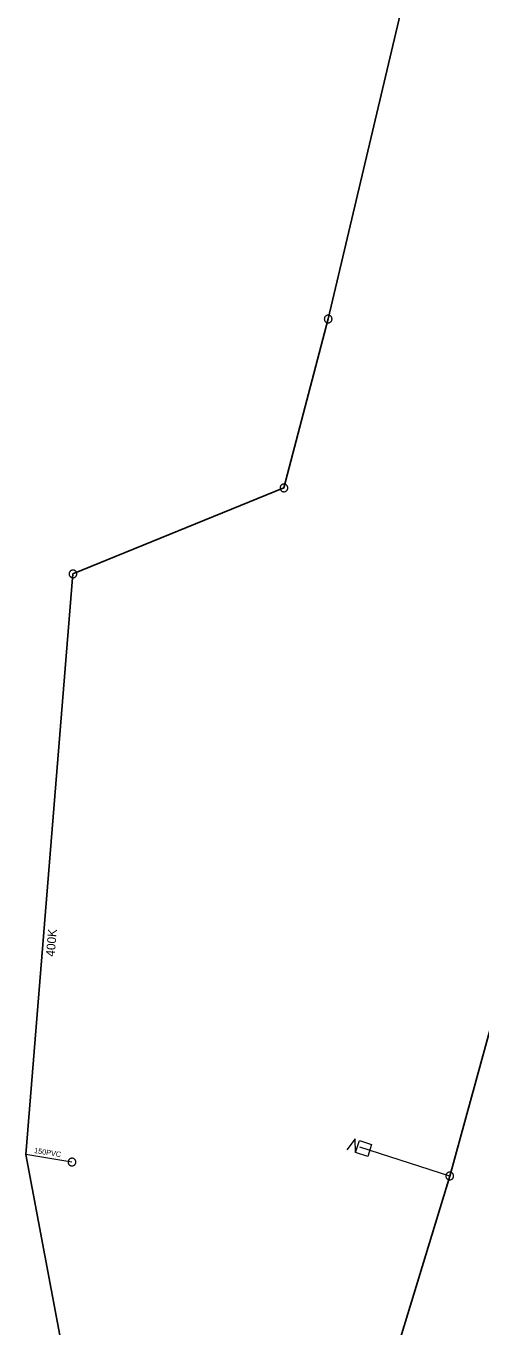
# Model space of a CAD drawing. Extents: x -741806 to -738704, y -1059275 to -1055387.
# Drawn here: x -740344.9 to -740293.4, y -1056915.4 to -1056767.8 of the extents above; entities that cross this region are included whole.
import ezdxf

# ---------------------------------------------------------------- set-up
doc = ezdxf.new("R2010")
doc.units = 0
doc.header["$LTSCALE"] = 0.4
for name, color, linetype, lineweight in [('2', 7, 'Continuous', 25), ('21', 7, 'Continuous', 13), ('3', 7, 'Continuous', 13), ('46', 7, 'Continuous', 13), ('51', 7, 'Continuous', 13), ('52', 7, 'Continuous', 25), ('56', 7, 'Continuous', 13), ('60', 7, 'Continuous', 13)]:
    doc.layers.add(name, color=color, linetype=linetype, lineweight=lineweight)
doc.layers.add('5', color=7, linetype='Continuous')
doc.layers.add('55', color=7, linetype='Continuous')

msp = doc.modelspace()

# ---------------------------------------------------------------- linework, layer by layer
at = {"layer": '2'}
for p, q in [((-740344.949, -1056895.875), (-740339.62, -1056830)), ((-740332.78, -1056960.44), (-740344.949, -1056895.875))]:
    msp.add_line(p, q, dxfattribs=at)
msp.add_lwpolyline([(-740339.62, -1056830), (-740315.66, -1056820.24), (-740310.64, -1056801.08), (-740301.43, -1056762.19), (-740297.32, -1056727.3), (-740286.155, -1056679.426), (-740260.146, -1056685.649), (-740223.28, -1056694.679), (-740203.5, -1056696.159)], dxfattribs=at)
at = {"layer": '21'}
msp.add_line((-740296.842, -1056898.301), (-740307.048, -1056895.04), dxfattribs=at)
at = {"layer": '3'}
for points in [[(-740310.528, -1056800.656), (-740310.572, -1056800.647), (-740310.618, -1056800.643), (-740310.664, -1056800.643), (-740310.709, -1056800.648), (-740310.754, -1056800.658), (-740310.798, -1056800.672), (-740310.839, -1056800.691), (-740310.879, -1056800.714), (-740310.915, -1056800.742), (-740310.949, -1056800.772), (-740310.98, -1056800.806), (-740311.007, -1056800.844), (-740311.029, -1056800.883), (-740311.048, -1056800.925), (-740311.062, -1056800.969), (-740311.071, -1056801.014), (-740311.075, -1056801.059), (-740311.076, -1056801.105), (-740311.07, -1056801.151), (-740311.06, -1056801.196), (-740311.046, -1056801.239), (-740311.027, -1056801.28), (-740311.004, -1056801.32), (-740310.977, -1056801.357), (-740310.946, -1056801.391), (-740310.911, -1056801.421), (-740310.875, -1056801.448), (-740310.835, -1056801.471), (-740310.793, -1056801.489), (-740310.749, -1056801.503), (-740310.705, -1056801.512), (-740310.659, -1056801.517), (-740310.613, -1056801.517), (-740310.567, -1056801.511), (-740310.523, -1056801.502), (-740310.479, -1056801.487), (-740310.438, -1056801.468), (-740310.398, -1056801.445), (-740310.362, -1056801.418), (-740310.328, -1056801.388), (-740310.297, -1056801.353), (-740310.27, -1056801.316), (-740310.247, -1056801.276), (-740310.229, -1056801.235), (-740310.215, -1056801.191), (-740310.206, -1056801.146), (-740310.201, -1056801.1), (-740310.201, -1056801.055), (-740310.207, -1056801.009), (-740310.217, -1056800.964), (-740310.231, -1056800.921), (-740310.249, -1056800.879), (-740310.273, -1056800.839), (-740310.3, -1056800.803), (-740310.331, -1056800.769), (-740310.365, -1056800.738), (-740310.402, -1056800.712), (-740310.443, -1056800.689), (-740310.484, -1056800.67), (-740310.527, -1056800.656)], [(-740315.254, -1056820.075), (-740315.273, -1056820.034), (-740315.297, -1056819.995), (-740315.325, -1056819.958), (-740315.356, -1056819.925), (-740315.391, -1056819.895), (-740315.428, -1056819.868), (-740315.468, -1056819.847), (-740315.511, -1056819.828), (-740315.554, -1056819.816), (-740315.599, -1056819.807), (-740315.645, -1056819.803), (-740315.691, -1056819.804), (-740315.736, -1056819.81), (-740315.781, -1056819.82), (-740315.824, -1056819.835), (-740315.866, -1056819.854), (-740315.905, -1056819.879), (-740315.941, -1056819.906), (-740315.975, -1056819.938), (-740316.005, -1056819.973), (-740316.03, -1056820.01), (-740316.052, -1056820.049), (-740316.07, -1056820.092), (-740316.084, -1056820.135), (-740316.093, -1056820.181), (-740316.096, -1056820.227), (-740316.096, -1056820.272), (-740316.09, -1056820.318), (-740316.079, -1056820.362), (-740316.064, -1056820.406), (-740316.045, -1056820.447), (-740316.021, -1056820.486), (-740315.993, -1056820.523), (-740315.961, -1056820.556), (-740315.928, -1056820.586), (-740315.89, -1056820.612), (-740315.85, -1056820.634), (-740315.807, -1056820.652), (-740315.764, -1056820.665), (-740315.719, -1056820.674), (-740315.673, -1056820.678), (-740315.627, -1056820.677), (-740315.582, -1056820.672), (-740315.537, -1056820.661), (-740315.494, -1056820.646), (-740315.452, -1056820.626), (-740315.413, -1056820.603), (-740315.377, -1056820.575), (-740315.344, -1056820.543), (-740315.314, -1056820.508), (-740315.288, -1056820.471), (-740315.265, -1056820.431), (-740315.248, -1056820.389), (-740315.234, -1056820.345), (-740315.226, -1056820.3), (-740315.222, -1056820.254), (-740315.223, -1056820.209), (-740315.229, -1056820.163), (-740315.239, -1056820.118), (-740315.253, -1056820.076)], [(-740339.578, -1056829.563), (-740339.623, -1056829.562), (-740339.669, -1056829.565), (-740339.715, -1056829.573), (-740339.758, -1056829.585), (-740339.801, -1056829.602), (-740339.842, -1056829.623), (-740339.879, -1056829.649), (-740339.915, -1056829.677), (-740339.946, -1056829.711), (-740339.975, -1056829.746), (-740340, -1056829.785), (-740340.021, -1056829.826), (-740340.036, -1056829.869), (-740340.048, -1056829.913), (-740340.054, -1056829.959), (-740340.056, -1056830.005), (-740340.053, -1056830.05), (-740340.046, -1056830.095), (-740340.033, -1056830.139), (-740340.016, -1056830.182), (-740339.994, -1056830.222), (-740339.97, -1056830.26), (-740339.94, -1056830.296), (-740339.908, -1056830.328), (-740339.871, -1056830.356), (-740339.833, -1056830.38), (-740339.792, -1056830.401), (-740339.749, -1056830.417), (-740339.704, -1056830.428), (-740339.659, -1056830.435), (-740339.614, -1056830.437), (-740339.568, -1056830.434), (-740339.523, -1056830.426), (-740339.478, -1056830.414), (-740339.436, -1056830.397), (-740339.395, -1056830.376), (-740339.358, -1056830.351), (-740339.322, -1056830.321), (-740339.291, -1056830.289), (-740339.262, -1056830.253), (-740339.237, -1056830.214), (-740339.216, -1056830.173), (-740339.2, -1056830.13), (-740339.189, -1056830.086), (-740339.183, -1056830.041), (-740339.181, -1056829.995), (-740339.183, -1056829.949), (-740339.191, -1056829.904), (-740339.204, -1056829.86), (-740339.221, -1056829.817), (-740339.243, -1056829.777), (-740339.267, -1056829.738), (-740339.297, -1056829.703), (-740339.329, -1056829.671), (-740339.366, -1056829.643), (-740339.404, -1056829.618), (-740339.445, -1056829.598), (-740339.488, -1056829.582), (-740339.533, -1056829.571), (-740339.577, -1056829.564)]]:
    msp.add_lwpolyline(points, dxfattribs=at)
at = {"layer": '46'}
msp.add_lwpolyline([(-740340.159, -1056896.648), (-740340.163, -1056896.693), (-740340.163, -1056896.739), (-740340.159, -1056896.785), (-740340.15, -1056896.829), (-740340.135, -1056896.873), (-740340.117, -1056896.915), (-740340.094, -1056896.954), (-740340.068, -1056896.992), (-740340.037, -1056897.026), (-740340.003, -1056897.056), (-740339.966, -1056897.084), (-740339.926, -1056897.107), (-740339.884, -1056897.125), (-740339.841, -1056897.14), (-740339.796, -1056897.149), (-740339.75, -1056897.155), (-740339.705, -1056897.154), (-740339.66, -1056897.15), (-740339.614, -1056897.14), (-740339.571, -1056897.126), (-740339.529, -1056897.107), (-740339.49, -1056897.085), (-740339.452, -1056897.058), (-740339.418, -1056897.028), (-740339.387, -1056896.994), (-740339.361, -1056896.956), (-740339.337, -1056896.918), (-740339.318, -1056896.875), (-740339.304, -1056896.832), (-740339.295, -1056896.787), (-740339.29, -1056896.742), (-740339.29, -1056896.696), (-740339.294, -1056896.65), (-740339.304, -1056896.605), (-740339.318, -1056896.562), (-740339.336, -1056896.52), (-740339.359, -1056896.481), (-740339.386, -1056896.443), (-740339.416, -1056896.409), (-740339.45, -1056896.379), (-740339.487, -1056896.351), (-740339.527, -1056896.328), (-740339.568, -1056896.309), (-740339.612, -1056896.295), (-740339.657, -1056896.286), (-740339.703, -1056896.28), (-740339.748, -1056896.28), (-740339.793, -1056896.285), (-740339.839, -1056896.295), (-740339.882, -1056896.309), (-740339.924, -1056896.328), (-740339.964, -1056896.349), (-740340.001, -1056896.377), (-740340.035, -1056896.407), (-740340.066, -1056896.441), (-740340.093, -1056896.479), (-740340.116, -1056896.517), (-740340.135, -1056896.56), (-740340.149, -1056896.603), (-740340.159, -1056896.647)], dxfattribs=at)
at = {"layer": '51'}
msp.add_lwpolyline([(-740296.958, -1056898.722), (-740296.914, -1056898.732), (-740296.869, -1056898.737), (-740296.822, -1056898.737), (-740296.777, -1056898.733), (-740296.732, -1056898.724), (-740296.688, -1056898.71), (-740296.647, -1056898.691), (-740296.606, -1056898.669), (-740296.57, -1056898.642), (-740296.536, -1056898.612), (-740296.504, -1056898.578), (-740296.477, -1056898.541), (-740296.453, -1056898.502), (-740296.435, -1056898.46), (-740296.421, -1056898.416), (-740296.41, -1056898.371), (-740296.405, -1056898.326), (-740296.405, -1056898.281), (-740296.41, -1056898.235), (-740296.419, -1056898.189), (-740296.433, -1056898.146), (-740296.451, -1056898.104), (-740296.474, -1056898.064), (-740296.5, -1056898.027), (-740296.531, -1056897.993), (-740296.565, -1056897.962), (-740296.601, -1056897.935), (-740296.642, -1056897.912), (-740296.683, -1056897.893), (-740296.727, -1056897.878), (-740296.771, -1056897.869), (-740296.816, -1056897.864), (-740296.863, -1056897.863), (-740296.908, -1056897.867), (-740296.953, -1056897.877), (-740296.997, -1056897.891), (-740297.038, -1056897.909), (-740297.079, -1056897.931), (-740297.115, -1056897.959), (-740297.149, -1056897.989), (-740297.18, -1056898.023), (-740297.208, -1056898.06), (-740297.231, -1056898.099), (-740297.25, -1056898.14), (-740297.264, -1056898.184), (-740297.275, -1056898.229), (-740297.279, -1056898.275), (-740297.28, -1056898.32), (-740297.275, -1056898.366), (-740297.265, -1056898.411), (-740297.251, -1056898.454), (-740297.234, -1056898.496), (-740297.211, -1056898.536), (-740297.185, -1056898.573), (-740297.154, -1056898.608), (-740297.12, -1056898.639), (-740297.083, -1056898.665), (-740297.043, -1056898.689), (-740297.002, -1056898.708), (-740296.959, -1056898.721)], dxfattribs=at)
at = {"layer": '52'}
msp.add_lwpolyline([(-740275.601, -1056823.152), (-740278.978, -1056835.415), (-740282.21, -1056845.104), (-740296.842, -1056898.301), (-740316.568, -1056963.017)], dxfattribs=at)
at = {"layer": '56'}
msp.add_line((-740339.727, -1056896.718), (-740344.949, -1056895.875), dxfattribs=at)
at = {"layer": '60'}
msp.add_lwpolyline([(-740307.534, -1056895.633), (-740307.561, -1056894.091), (-740308.52, -1056895.318)], dxfattribs=at)
msp.add_lwpolyline([(-740305.709, -1056894.71), (-740306.151, -1056896.093), (-740307.534, -1056895.651), (-740307.092, -1056894.268)], close=True, dxfattribs=at)

# ---------------------------------------------------------------- texts
at = {"layer": '5'}
msp.add_text('400K', height=1, rotation=85, dxfattribs=at).set_placement((-740341.706, -1056873.443))
at = {"layer": '55'}
msp.add_text('150PVC', height=0.6, rotation=351, dxfattribs=at).set_placement((-740344.061, -1056895.683))

doc.saveas('drawing.dxf')
